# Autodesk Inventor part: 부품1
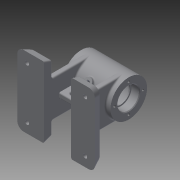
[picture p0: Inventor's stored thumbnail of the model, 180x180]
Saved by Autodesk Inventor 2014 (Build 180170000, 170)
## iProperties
Created: 2016-07
Part Number: 부품1
Material: 일반
Document SubType Name: Modeling
Designer: net
Density: 1 g/cm^3
Appearance: 기본값
Author: net
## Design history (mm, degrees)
sketch "스케치1"
  geometry: L1 (0, 0)-(70, 0); L2 (70, 0)-(70, 27); L3 (70, 27)-(0, 27); L4 (0, 27)-(0, 0); L5 (0, 16)-(11.7, 16); L6 (12, 15.7)-(12, 14); L7 (12, 14)-(14, 14); L8 (14, 14)-(14, 19); L9 (17, 22)-(53, 22); L10 (56, 19)-(56, 14); L11 (56, 14)-(58, 14); L12 (58, 14)-(58, 15.7); L13 (58.3, 16)-(70, 16); A1 r 0.3 centre (11.7, 15.7) between (12, 15.7) and (11.7, 16); A2 r 0.3 centre (58.3, 15.7) between (58.3, 16) and (58, 15.7); A3 r 3 centre (53, 19) between (56, 19) and (53, 22); A4 r 3 centre (17, 19) between (17, 22) and (14, 19)
  constraints: 26 end point, 8 point on circle, 8 tangent, 7 parallel, 4 centre point, 4 perpendicular, 3 horizontal, 2 equal radius, 2 point on line, 1 vertical
  dimensions: "d3" = 70 distance of L3.end L2.end; "d4" = 27 distance of L2.end L1.end; "d5" = 12 distance between parallel lines of L6 L4; "d6" = 12 distance between parallel lines of L2 L12; "d7" = 22 distance between parallel lines of L1 L9; "d8" = 42 distance between parallel lines of L10 L8; "d9" = 2 distance of L6.end L7.end; "d10" = 16 distance between parallel lines of L1 L13; "d12" = 0.3 radius of A1; "d13" = 3 radius of A3; "d14" = 14 distance between parallel lines of L1 L7
revolve "회전1" sketch "스케치1" stored, may be unused: angle "d15" = 90 deg
node "작업 평면1"
sketch "스케치2"
  geometry: L1 (0, 0)-(-48, 0); L2 (-70, 27)-(-70, -27) reference; C1 r 5 at (-48, 0)
  constraints: 2 end point, 1 centre point, 1 coincident, 1 horizontal
  dimensions: "d18" = 10 diameter of C1; "d146" = 22 distance from line of L1.end L2
extrude "돌출1" join sketch "스케치2" stored distance "d19" = 10; taper "d20" = 0 deg
node "작업 평면2"
sketch "스케치5"
  geometry: L1 (0, 0)-(-35, 0); L2 (20, -50)-(-90, -50); L3 (-90, -50)-(-90, 50); L4 (-90, 50)-(20, 50); L5 (20, 50)-(20, -50); L6 (20, -50)-(-90, 50); L7 (-90, -50)-(20, 50); L8 (-90, -50)-(-90, -25); L9 (-90, 15)-(-90, 50); L10 (20, 50)-(20, 15); L11 (20, -25)-(20, -50); L12 (-55, -50)-(-55, 50); L13 (-15, 50)-(-15, -50); L14 (-15, 50)-(20, 50); L15 (-55, 50)-(-90, 50); L16 (-90, -50)-(-55, -50); L17 (-15, -50)-(20, -50)
  constraints: 34 end point, 6 collinear, 4 parallel, 4 point on line, 2 horizontal, 2 midpoint, 1 perpendicular
  dimensions: "d22" = 35 distance of L1.start L1.end; "d23" = 110 distance of L3.end L4.end; "d24" = 100 distance of L2.end L3.end; "d33" = 35 distance between parallel lines of L3 L12; "d34" = 35 distance between parallel lines of L5 L13
extrude "돌출3" join sketch "스케치5" distance "d35" = 12; taper "d36" = 0 deg
feature "면 기울기3" dims angle "d37" = 20 deg
feature "면 기울기4" dims angle "d38" = 20 deg
feature "면 기울기5" dims angle "d39" = 20 deg
sketch "스케치7"
  geometry: L1 (0, 0)-(-35, 0); L2 (-35, 0)-(-90, 0); L3 (-63, -27)-(-7, -27); L4 (-7, -27)-(-7, 27); L5 (-7, 27)-(-63, 27); L6 (-63, 27)-(-63, -27); L7 (-63, -27)-(-7, 27); L8 (-7, -27)-(-63, 27); L9 (-55, -45.632)-(-55, 50) reference; L10 (-55, 27)-(-55, 4); L11 (-55, -4)-(-55, -27); L12 (-15, -27)-(-15, -4); L13 (-15, 4)-(-15, 27); L14 (-55, 4)-(-15, 4); L15 (-15, -4)-(-55, -4); L16 (-7, 27)-(-15, 27); L17 (-55, 27)-(-63, 27); L18 (-63, -27)-(-55, -27); L19 (-15, -27)-(-7, -27); 1 further point
  constraints: 36 end point, 7 parallel, 4 perpendicular, 4 point on line, 3 collinear, 2 horizontal, 2 midpoint, 1 coincident
  dimensions: "d56" = 35 distance of L1.start L1.end; "d57" = 55 distance of L1.end L2.end; "d60" = 54 distance of L3.end L4.end; "d61" = 8 distance between parallel lines of L9 L6; "d65" = 8 distance between parallel lines of L15 L14; "d66" = 4 distance between parallel lines of L15 L2; "d67" = 8 distance of L12.start L3.end; "d68" = 8 distance of L4.end L13.end
extrude "돌출5" join sketch "스케치7" stored distance "d69" = 12; taper "d70" = 0 deg
sketch "스케치8"
  geometry: L1 (0, 43.298)-(40, 43.298) reference; L2 (40, 43.298)-(40, 0) reference; L3 (0, 0)-(40, 0); L4 (40, 0)-(40, 22.298); L5 (40, 22.298)-(0, 22.298); L6 (0, 22.298)-(0, 0); 1 further point
  constraints: 8 end point, 2 parallel, 1 horizontal, 1 perpendicular, 1 point on line
  dimensions: "d71" = 21 distance between parallel lines of L5 L1
extrude "돌출6" cut sketch "스케치8" distance "d72" = 12; taper "d73" = 0 deg
node "작업 평면3"
sketch "스케치9"
  geometry: L1 (0, 0)-(-70.132, 0); L2 (0, 0)-(-25.441, 15.898); L3 (-22.262, 20.986)-(-25.441, 15.898); L4 (-18.657, 11.658)-(-15.478, 16.747); L5 (-18.657, 11.658)-(-25.441, 15.898); L6 (-22.262, 20.986)-(-15.478, 16.747); C1 r 27 at (0, 0) reference
  constraints: 12 end point, 2 parallel, 1 collinear, 1 horizontal, 1 perpendicular, 3 other
  dimensions: "d79" = 5 dimension on C1 (derived); "d80" = 30 distance of L2.start L2.end; "d81" = 32 deg angle of L1 L2; "d83" = 6 distance between parallel lines of L2 L6
revolve "회전2" sketch "스케치9" stored, may be unused: angle "d84" = 90 deg
sketch "스케치12" dims "d85" = 42
  geometry: C1 r 27 at (0, 0) reference; 2 further points
  constraints: 1 coincident, 1 vertical alignment, 2 other
hole "구멍1" sketch "스케치12" at (0, 21) diameter "d86" = 3.242; stored, may be unused: countersink angle "d90" = 90 deg, drill point angle "d92" = 118 deg; dims "d87" = 8, "d88" = 4, "d89" = 2, "d91" = 10
hole "구멍2" diameter "d98" = 5.188; stored, may be unused: countersink angle "d102" = 90 deg, drill point angle "d104" = 118 deg; dims "d96" = 10, "d97" = 10, "d99" = 8, "d100" = 4, "d101" = 2, "d103" = 20
hole "구멍3" diameter "d107" = 5.188; stored, may be unused: countersink angle "d111" = 90 deg, drill point angle "d113" = 118 deg; dims "d105" = 10, "d106" = 10, "d108" = 8, "d109" = 4, "d110" = 2, "d112" = 20
fillet "모깎기2" dims "d115" = 10
fillet "모깎기3" dims "d116" = 2
fillet "모깎기4" dims "d117" = 2
sketch "스케치13"
  geometry: 17 further points; 4 other entities
  constraints: 4 coincident, 4 other
hole "구멍4" sketch "스케치13" diameter "d118" = 6; stored, may be unused: countersink angle "d122" = 90 deg, drill point angle "d124" = 118 deg; dims "d119" = 8, "d120" = 10, "d121" = 4, "d123" = 20
hole "구멍5" sketch "스케치13" diameter "d125" = 6; stored, may be unused: countersink angle "d129" = 90 deg, drill point angle "d131" = 118 deg; dims "d126" = 8, "d127" = 10, "d128" = 4, "d130" = 20
sketch "스케치14" dims "d22" = 35
  geometry: L1 (40, 0)-(0, 0) reference; L2 (0.03, 17.33)-(39.97, 17.33) reference; L3 (12, 7.702)-(28, 7.702); L4 (12, 4.202)-(28, 4.202); L5 (28, 11.202)-(12, 11.202); L6 (-29.971, -24.298)-(-2, -24.298) reference; L7 (20, 17.33)-(20, -15.165); A1 r 3.5 centre (12, 7.702) between (12, 11.202) and (12, 4.202); A2 r 3.5 centre (28, 7.702) between (28, 4.202) and (28, 11.202); 3 further points
  constraints: 10 end point, 5 point on circle, 4 tangent, 2 centre point, 2 midpoint, 2 parallel, 1 perpendicular, 1 point on line
  dimensions: "d132" = 16 distance of L3.end L3.start; "d133" = 3.5 radius of A1; "d134" = 32 distance from line of L6 point (20, 7.702)
extrude "돌출7" cut sketch "스케치14" distance "d135" = 12; taper "d136" = 0 deg
fillet "모깎기5" dims "d137" = 2
chamfer "모따기1" distance "d138" = 1; stored, may be unused: second distance "d139" = 2, angle "d140" = 45 deg
node "작업 평면11"
sketch "스케치16"
  geometry: L1 (-40, 100)-(-30, 100) reference; L2 (-57, 97)-(-57, 43) reference; 2 further points
  constraints: 1 other
  dimensions: "d142" = 30 distance from line of L1 point (-22, 70); "d143" = 35 distance from line of L2 point (-22, 70)
feature "엠보싱1" sketch "스케치16" dims "d3" = 70, "d4" = 27, "d5" = 12, "d6" = 12, "d7" = 22, "d8" = 42, "d9" = 2, "d10" = 16, "d12" = 0.3, "d13" = 3, "d14" = 14, "d144" = 0.5, "d145" = 0
node "솔리드1"
pattern_circular "원형 패턴1" dims angle "d94" = 360 deg
mirror "대칭1"
other parameters: "d45" = 8, "d46" = 8, "d58" = 35, "d64" = 8, "d74" = 35
